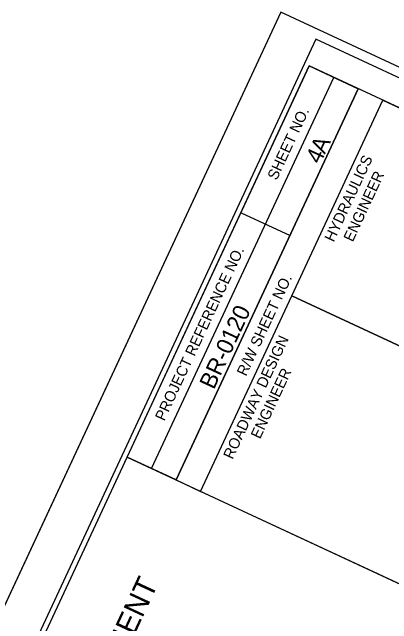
# Model space of a CAD drawing. Extents: x 2532214 to 2533961, y 714631 to 717266.
# Drawn here: x 2532799.9 to 2532975.7, y 716336.1 to 716619.6 of the extents above; entities that cross this region are included whole.
import ezdxf

# ---------------------------------------------------------------- set-up
doc = ezdxf.new("R2010")
doc.units = 0
for name, color, linetype in [('Scratch_Level_0', 7, 'Continuous'), ('Sheet Cutting Line CELL', 7, 'Continuous'), ('Sheet Data Field CELL', 7, 'Continuous'), ('Sheet Layout Plan Border', 7, 'Continuous'), ('Sheet Plan And Profile CELL', 7, 'Continuous'), ('Sheet Plot Border Inside CELL', 7, 'Continuous'), ('Sheet Plot Border Outside CELL', 7, 'Continuous')]:
    doc.layers.add(name, color=color, linetype=linetype)

msp = doc.modelspace()

# ---------------------------------------------------------------- linework, layer by layer
at = {"layer": 'Scratch_Level_0'}
msp.add_lwpolyline([(2532325.86, 715280.03), (2532853.13, 716413.33), (2533042.37, 716325.28), (2533126.76, 716506.66), (2533345.52, 716404.88), (2533436.18, 716362.7), (2533229.49, 715918.43), (2532824.53, 715048.02)], close=True, dxfattribs=at)
at = {"layer": 'Sheet Cutting Line CELL'}
msp.add_line((2532924.28, 716619.61), (2532214.14, 715093.22), dxfattribs=at)
at = {"layer": 'Sheet Layout Plan Border'}
msp.add_lwpolyline([(2532801.87, 715058.57), (2532325.86, 715280.03), (2532853.13, 716413.33), (2533042.37, 716325.28), (2533105.67, 716461.33), (2533392.43, 716327.91)], close=True, dxfattribs=at)
at = {"layer": 'Sheet Plan And Profile CELL'}
for p, q in [((2532864.5, 716408.03), (2532948.89, 716589.41)), ((2532875.84, 716402.76), (2532960.22, 716584.14)), ((2532905.92, 716526.69), (2532928.59, 716516.14)), ((2532929.37, 716488.2), (2533031.33, 716440.77)), ((2532875.84, 716402.76), (2532887.17, 716397.49))]:
    msp.add_line(p, q, dxfattribs=at)
for points in [[(2532937.51, 716594.71), (2532304.77, 715234.69), (2533256.78, 714791.77), (2533889.52, 716151.79)], [(2532853.13, 716413.33), (2532937.51, 716594.71), (2532960.22, 716584.14), (2532875.84, 716402.76)], [(2532929.37, 716488.2), (2532971.56, 716578.87), (2533073.56, 716531.41), (2533031.38, 716440.74)], [(2532887.17, 716397.49), (2532929.37, 716488.2), (2533031.38, 716440.74), (2532989.17, 716350.03)]]:
    msp.add_lwpolyline(points, close=True, dxfattribs=at)
at = {"layer": 'Sheet Plot Border Inside CELL'}
msp.add_lwpolyline([(2533194.3, 714651.54), (2533897.06, 716162.07), (2532940.52, 716607.1), (2532237.75, 715096.57)], close=True, dxfattribs=at)
at = {"layer": 'Sheet Plot Border Outside CELL'}
msp.add_lwpolyline([(2533206.95, 714631.32), (2533917.09, 716157.71), (2532924.28, 716619.61), (2532214.14, 715093.22)], close=True, dxfattribs=at)

# ---------------------------------------------------------------- texts
at = {"layer": 'Sheet Data Field CELL'}
for s, height, p in [('A', 7.75, (2532944.7, 716553.51)), ('4', 7.75, (2532942.54, 716548.86)), ('BR-0120', 7.75, (2532893.32, 716444.32)), ('** DETAIL FOR RIGHT OF WAY MONUMENT', 10, (2532750.79, 716103.41))]:
    msp.add_text(s, height=height, rotation=65.05, dxfattribs=at).set_placement(p)
at = {"layer": 'Sheet Plan And Profile CELL'}
for s, height, p in [('SHEET NO.', 5, (2532922.42, 716541.4)), ('HYDRAULICS', 5, (2532948.84, 716512.73)), ('ENGINEER', 5, (2532957.65, 716512.82)), ('PROJECT REFERENCE NO.', 5.0001, (2532870.38, 716429.78)), ('R/W SHEET NO.', 5.0001, (2532908.22, 716450.56)), ('ROADWAY DESIGN', 5.0001, (2532901.97, 716412)), ('ENGINEER', 5, (2532914.7, 716421.46))]:
    msp.add_text(s, height=height, rotation=65.05, dxfattribs=at).set_placement(p)

doc.saveas('drawing.dxf')
